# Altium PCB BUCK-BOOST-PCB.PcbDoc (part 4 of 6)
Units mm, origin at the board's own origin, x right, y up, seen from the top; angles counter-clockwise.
Board outline 99.9 x 67.48 mm, 4 copper layers (Top Layer, POWER, GND, Bottom Layer); 181 components, 110 nets, 560 pads, 389 vias.
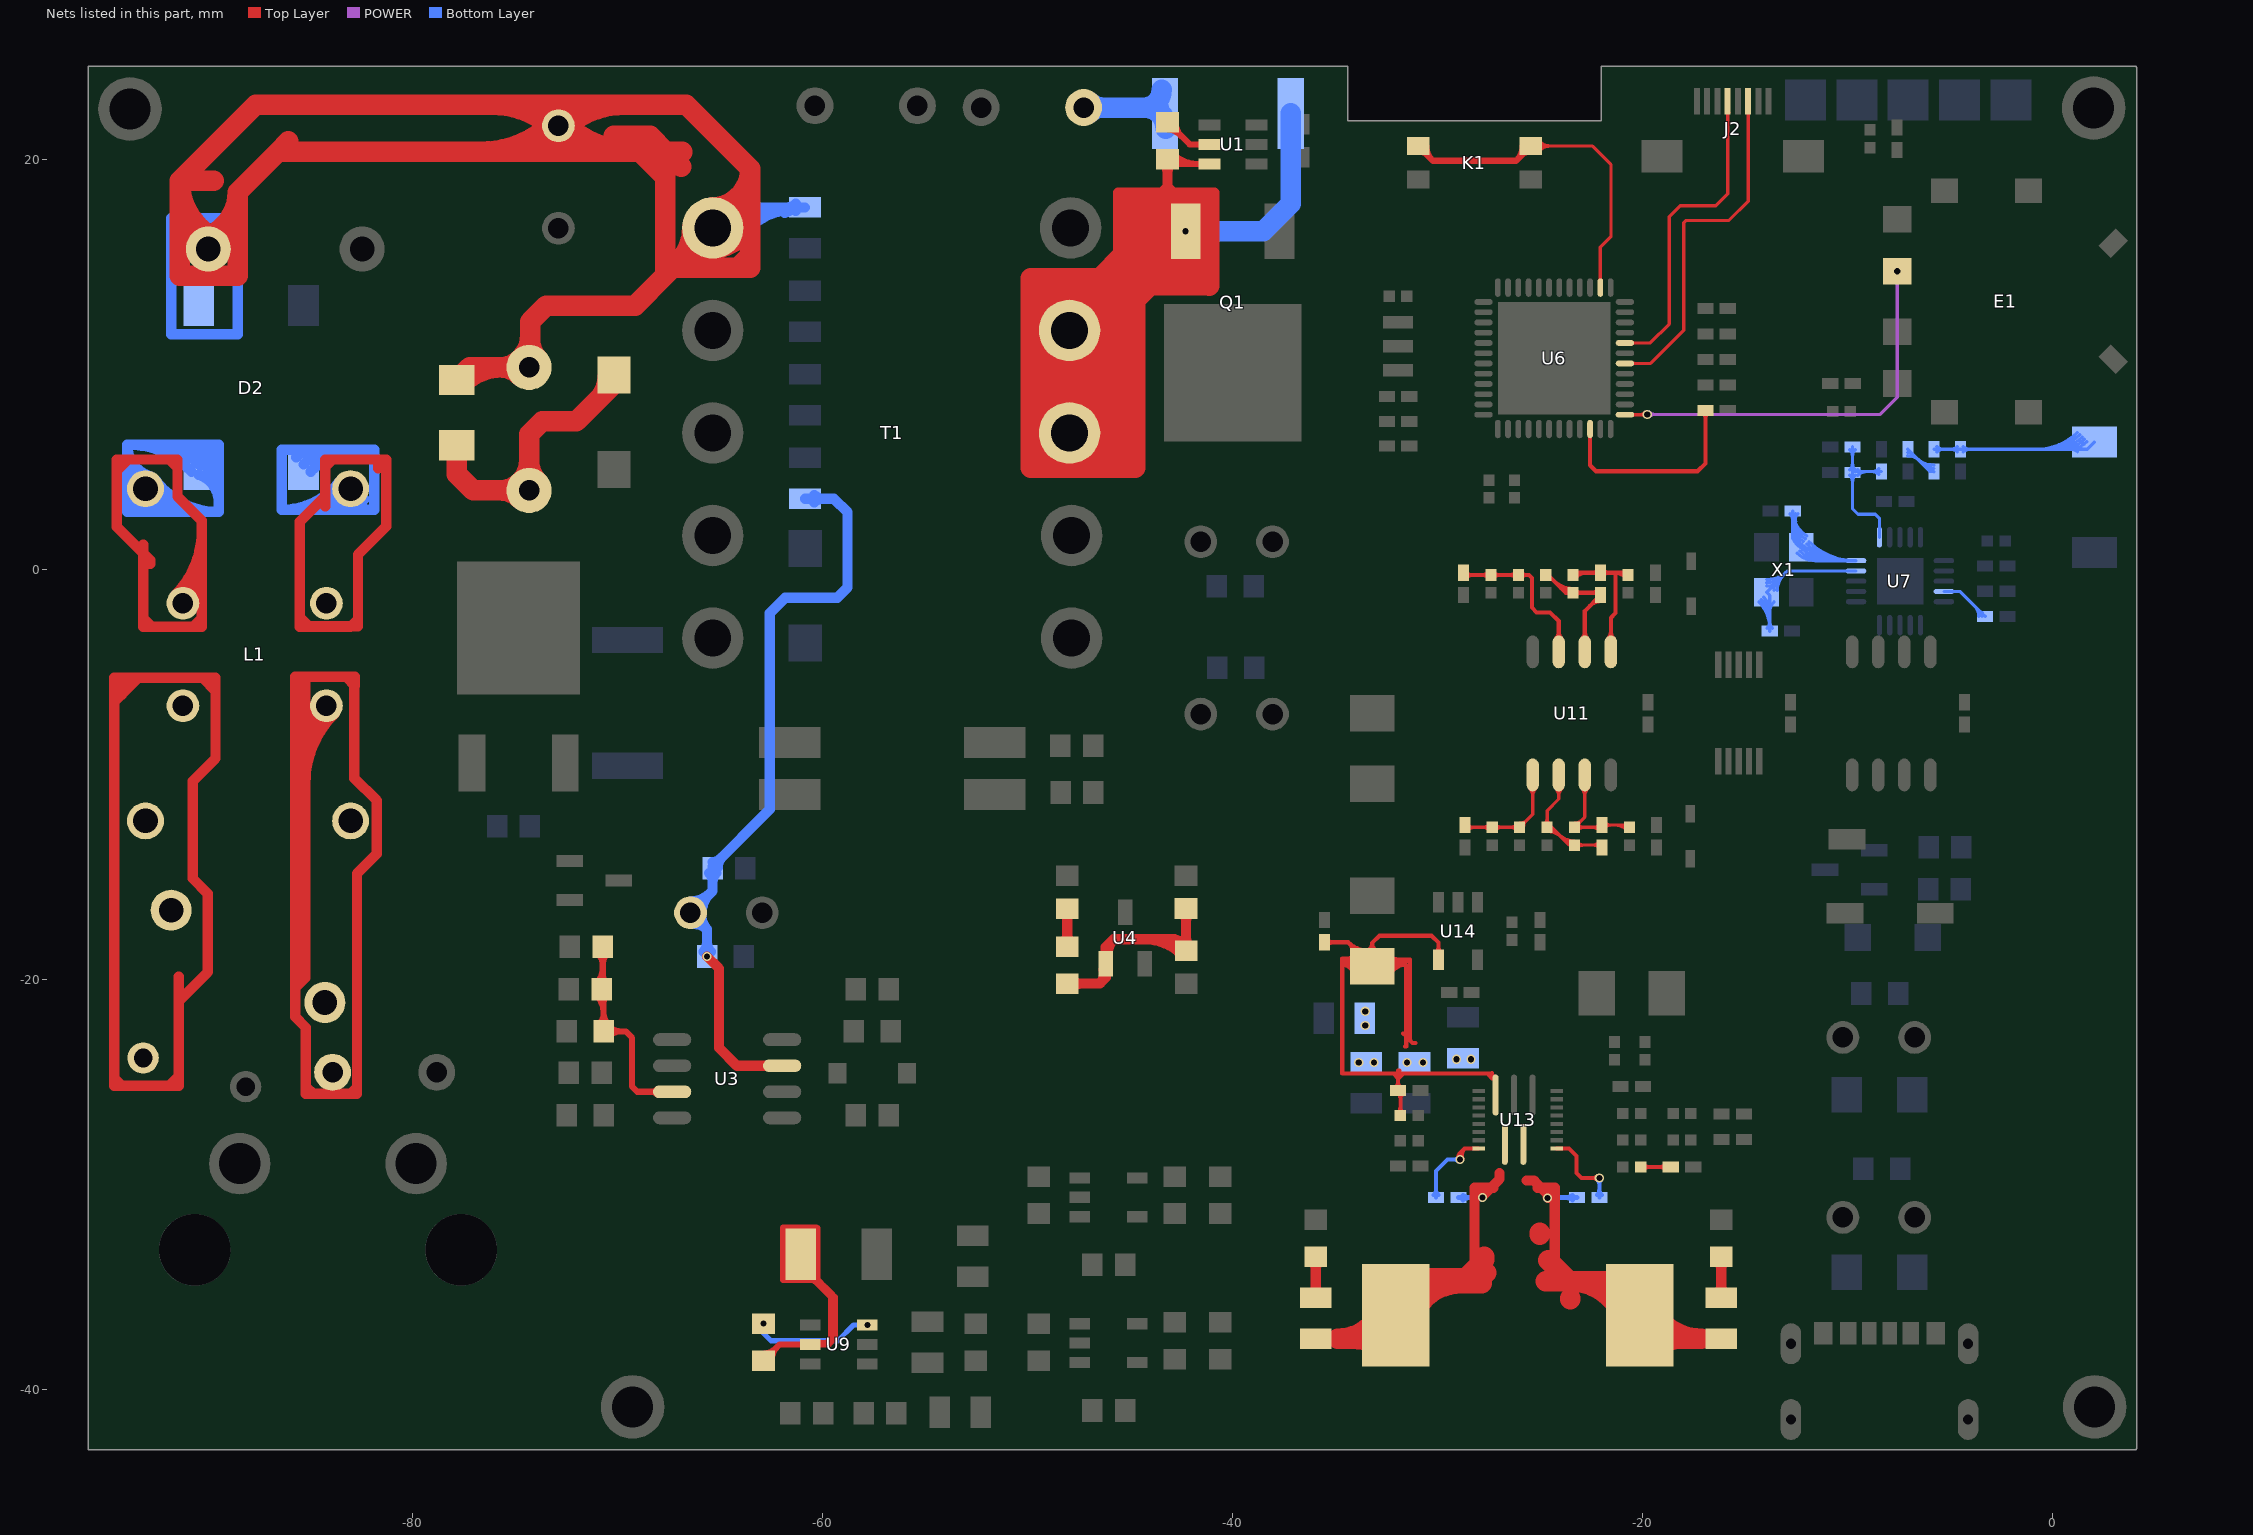
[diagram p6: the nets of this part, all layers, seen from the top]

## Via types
v1: diameter 0.45, hole 0.3, Top Layer to Bottom Layer, 389 vias

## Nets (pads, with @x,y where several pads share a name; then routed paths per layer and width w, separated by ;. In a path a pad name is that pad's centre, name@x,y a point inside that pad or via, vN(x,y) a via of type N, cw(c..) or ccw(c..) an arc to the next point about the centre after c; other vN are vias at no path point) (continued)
ISENSE: C15.2 R11.2 R19.2 U3.3 | length 17.4
  Top Layer w0.3: R11.2@-71.008,-20.762 cw(c-71.852,-21.605) -70.659,-21.605 ; R11.2@-71.008,-20.165 ccw(c-71.745,-19.428) -70.703,-19.428 ; R19.2@-70.951,-18.691 cw(c-71.549,-19.289) -70.703,-19.289 cw(c-69.858,-19.289) R19.2@-70.456,-18.691 ; C15.2@-70.907,-22.216 ccw(c-71.505,-21.618) -70.659,-21.618 ccw(c-69.813,-21.618) C15.2@-70.411,-22.216 ; -70.703,-19.705 ccw(c-70.053,-19.705) R11.2@-70.513,-20.165 ; R19.2@-70.703,-18.392 -70.703,-20.406 R11.2@-70.761,-20.463 -70.659,-20.565 C15.2@-70.659,-22.515 -69.583,-22.515 -69.27,-22.828 -69.27,-25.207 -69.017,-25.46 U3.3@-67.317,-25.46 ; -70.659,-21.115 cw(c-70.16,-21.115) R11.2@-70.513,-20.762 ; C15.2@-70.411,-22.763 cw(c-69.813,-23.361) -69.813,-22.515 cw(c-69.813,-21.669) C15.2@-70.411,-22.267 ; U3.3@-68.051,-25.576 ccw(c-68.332,-25.858) -68.332,-25.46 ccw(c-68.332,-25.061) U3.3@-68.051,-25.343
K1: E1.S U6.25 | length 21.7
  Top Layer w0.16: U6.25@-20.847,7.563 -19.773,7.563 v1(-19.759,7.577) ; U6.25@-20.495,7.52 cw(c-20.392,7.418) -20.392,7.563 cw(c-20.392,7.708) U6.25@-20.495,7.605 ; -20.143,7.563 ccw(c-20.143,7.961) v1@-19.861,7.679 ; -20.075,7.563 cw(c-20.075,7.261) v1@-19.861,7.474
  POWER w0.16: v1(-19.759,7.577) -8.402,7.577 -7.563,8.416 v1(-7.563,14.562) ; v1@-19.656,7.474 cw(c-19.409,7.227) -19.409,7.577 cw(c-19.409,7.927) v1@-19.656,7.679 ; v1@-7.665,14.46 cw(c-7.913,14.212) -7.563,14.212 cw(c-7.213,14.212) v1@-7.46,14.46
K2: K1.1 K1.2 U6.38 | length 21.1
  Top Layer w0.16: K1.2@-25.435,20.666 -22.426,20.666 -21.53,19.77 -21.53,16.245 -22.046,15.729 U6.38@-22.046,13.763 ; K1.2@-25.183,20.527 cw(c-24.845,20.189) -24.845,20.666 cw(c-24.845,21.143) K1.2@-25.183,20.806 ; K1.2@-25.069,20.413 cw(c-24.459,19.803) -24.459,20.666 cw(c-24.459,21.529) K1.2@-25.069,20.919 ; U6.38@-22.088,14.115 ccw(c-22.191,14.218) -22.046,14.218 ccw(c-21.901,14.218) U6.38@-22.004,14.115
  Top Layer w0.3: K1.1@-30.935,20.666 -30.215,19.947 -26.154,19.947 K1.2@-25.435,20.666 ; K1.1@-30.822,20.379 cw(c-30.822,19.956) K1.1@-30.524,20.255 ; K1.1@-30.535,20.666 ccw(c-29.569,20.666) -30.252,19.983 ; -26.118,19.983 ccw(c-26.8,20.666) K1.2@-25.835,20.666 ; K1.2@-25.846,20.255 cw(c-25.547,19.956) K1.2@-25.547,20.379
LCD_BCK: J2.3 U6.30 | length 17.7
  Top Layer w0.16: U6.30@-20.847,10.065 -19.595,10.065 -17.973,11.687 -17.973,16.921 -17.856,17.038 -15.773,17.038 -14.838,17.973 J2.3@-14.838,22.85 ; U6.30@-20.495,10.022 cw(c-20.392,9.92) -20.392,10.065 cw(c-20.392,10.21) U6.30@-20.495,10.107 ; J2.3@-14.887,22.301 cw(c-15.007,22.181) -14.838,22.181 cw(c-14.669,22.181) J2.3@-14.788,22.301
LCD_RST: J2.5 U6.32 | length 16.1
  Top Layer w0.16: U6.32@-20.847,11.063 -19.615,11.063 -18.693,11.985 -18.693,17.219 -18.154,17.758 -16.419,17.758 -15.838,18.339 J2.5@-15.838,22.85 ; U6.32@-20.495,11.02 cw(c-20.392,10.918) -20.392,11.063 cw(c-20.392,11.208) U6.32@-20.495,11.105 ; J2.5@-15.887,22.301 cw(c-16.007,22.181) -15.838,22.181 cw(c-15.669,22.181) J2.5@-15.788,22.301
MVCC: C12.1 C13.1 R5.2 R8.1 U3.7 | length 44.7
  Top Layer w0.5: v1(-65.616,-18.861) -65.033,-19.444 -65.033,-23.313 -64.157,-24.19 U3.7@-61.952,-24.19
  Bottom Layer w0.5: C13.1@-66.422,-16.18 ccw(c-66.422,-14.852) -65.483,-15.791 ccw(c-64.544,-16.73) C13.1@-65.872,-16.73 ; C13.1@-66.36,-17.276 cw(c-66.257,-18.178) -65.616,-17.536 ; C13.1@-65.876,-16.792 ccw(c-64.974,-16.894) -65.616,-17.536 ; C12.1@-65.793,-18.633 ccw(c-66.22,-18.205) -65.616,-18.205 ccw(c-65.011,-18.205) C12.1@-65.439,-18.633 ; v1(-65.616,-18.861) -65.616,-17.536 ; R5.2@-65.521,-14.786 cw(c-65.949,-15.213) -65.344,-15.213 cw(c-64.74,-15.213) R5.2@-65.167,-14.786 ; R5.2@-65.344,-14.257 ccw(c-65.344,-13.741) R5.2@-64.98,-14.106 ; R5.2@-65.094,-14.507 cw(c-64.4,-14.507) R5.2@-64.89,-14.017 ; R8.1@-60.834,3.466 -59.426,3.466 -58.76,2.8 -58.76,-0.86 -59.263,-1.363 -61.807,-1.363 -62.556,-2.112 -62.556,-11.683 -65.344,-14.47 R5.2@-65.344,-14.558 -65.344,-15.651 C13.1@-66.422,-16.73 -65.616,-17.536 ; R8.1@-60.383,3.289 cw(c-59.955,2.861) -59.955,3.466 cw(c-59.955,4.07) R8.1@-60.383,3.643
NetC1_2: C1.2 R1.1 | length 13.7
  Bottom Layer w0.5: R1.1@-43.573,22.545 R1.1@-43.283,22.254
  Bottom Layer w1: C1.2@-47.247,22.545 -44.307,22.545 ; C1.2@-46.964,22.262 cw(c-46.282,21.579) -46.282,22.545 cw(c-46.282,23.511) C1.2@-46.964,22.828 ; -44.325,22.545 cw(c-44.325,21.212) R1.1@-43.383,22.154 ; R1.1@-43.573,22.545 -44.289,22.545 ; R1.1@-43.438,23.414 cw(c-44.307,23.414) -44.289,22.545 ; R1.1@-43.245,21.501 ccw(c-44.289,21.501) -44.289,22.545 ; -44.307,22.545 cw(c-44.307,21.257) -43.384,22.156 ccw(c-44.307,21.257) -44.307,22.545 ; -44.307,22.545 ccw(c-44.307,23.414) -44.289,22.545 ; -44.307,22.545 -44.289,22.545 ; -44.288,22.545 cw(c-44.288,21.299) -43.385,22.157 ccw(c-44.288,21.299) -44.288,22.545
NetC2_1: C2.1 D1.2 R2.1 | length 19.3
  Top Layer w1: C2.1@-77.813,6.069 -77.813,4.667 -77.015,3.87 R2.1@-74.294,3.87 -74.294,6.612 -73.655,7.25 -71.984,7.25 -70.156,9.078 D1.2@-70.156,9.495 ; R2.1@-74.718,3.446 ccw(c-75.742,2.421) -75.742,3.87 ccw(c-75.742,5.318) -74.718,4.294 ccw(c-75.742,5.318) -74.294,5.318 ccw(c-72.845,5.318) R2.1@-73.869,4.294 ; -70.917,8.318 ccw(c-72.003,9.404) D1.2@-70.466,9.404
NetC2_2: C2.2 C10.1 C11.1 D2.1 R2.2 R3.2 T1.1 | length 194.4
  Top Layer w1: -91.33,17.298 ccw(c-89.052,17.298) C11.1@-90.126,15.29 ; C11.1@-90.119,16.214 ccw(c-90.819,18.42) -88.505,18.42 ; C11.1@-89.817,15.261 ccw(c-90.385,17.054) -88.505,17.054 ; -89.662,18.968 -91.33,18.968 ; C11.1@-89.655,16.172 cw(c-88.159,18.967) -91.33,18.967 ; -86.03,20.895 -86.537,20.389 ; C2.2@-77.813,9.254 -77.198,9.87 R2.2@-74.294,9.87 -74.243,9.921 -74.243,12.107 -73.463,12.887 -69.121,12.887 -67.645,14.362 ; C2.2@-77.52,9.083 cw(c-75.62,7.183) -75.62,9.87 ; -76.641,20.389 ccw(c-76.641,25.432) C10.1@-73.075,21.866 ; -76.062,22.678 cw(c-76.062,18.455) C10.1@-73.075,21.441 ; R2.2@-74.718,9.446 ccw(c-75.742,8.421) -75.742,9.87 ccw(c-75.742,11.318) -74.718,10.294 ccw(c-75.865,11.441) -74.243,11.441 ; -74.243,11.196 ccw(c-72.968,11.196) R2.2@-73.869,10.294 ; -74.227,20.389 ccw(c-74.227,23.018) C10.1@-72.368,21.159 ; -73.648,22.678 cw(c-73.648,20.869) C10.1@-72.368,22.148 ; C10.1@-73.358,21.159 ccw(c-71.499,23.018) -71.499,20.389 ; C10.1@-73.358,22.148 cw(c-72.078,20.869) -72.078,22.678 ; C10.1@-72.651,21.441 cw(c-69.664,18.455) -69.664,22.678 ; C10.1@-72.651,21.866 ccw(c-69.085,25.432) -69.085,20.389 ; -70.175,21.163 -69.659,21.163 ; -66.879,19.652 -67.616,20.389 ; -66.816,20.37 -66.835,20.389 -67.616,20.389 ; T1.1@-66.336,16.671 cw(c-68.751,16.671) -67.044,14.964 cw(c-65.336,13.257) T1.1@-65.336,15.671 ; T1.1@-65.355,17.671 ccw(c-65.391,19.552) -63.51,19.552 ; T1.1@-65.317,15.672 ccw(c-65.352,17.513) -63.51,17.513 ; -63.51,18.533 cw(c-65.372,18.533) -65.336,16.671 -67.187,14.821 ; -91.33,18.968 -91.33,14.333 -88.505,14.333 -88.505,18.42 ; -91.33,18.968 -87.619,22.678 -66.637,22.678 -63.51,19.552 ; -88.505,18.42 -86.537,20.389 ; -86.537,20.389 -68.885,20.389 ; -69.659,21.163 -68.391,21.163 -67.645,20.418 ; -69.659,21.163 -68.885,20.389 ; -68.885,20.389 -67.645,20.389 ; -68.885,20.389 -67.645,19.149 ; -67.645,14.362 -67.187,14.821 ; -67.645,14.362 -67.645,19.149 ; -67.645,19.149 -67.645,20.389 ; -67.645,20.389 -67.616,20.389 ; -67.645,20.389 -67.645,20.418 ; -67.645,20.418 -67.616,20.389 ; -67.187,14.821 -67.092,14.726 -64.077,14.726 ; -64.077,14.726 -63.51,14.726 -63.51,15.345 ; -64.077,14.726 -64.077,14.779 -63.51,15.345 ; -63.51,15.345 -63.51,19.552
  Bottom Layer w0.5: T1.1@-65.536,16.821 cw(c-63.835,15.545) -63.835,17.672 ; T1.1@-65.336,16.671 -64.336,17.672 R3.2@-60.834,17.672 ccw(c-60.834,13.294) T1.1@-64.336,15.921 ; T1.1@-65.136,16.521 cw(c-62.835,14.795) -62.835,17.672 ; T1.1@-64.736,16.221 cw(c-61.835,14.045) -61.835,17.672 ; -61.837,17.404 ccw(c-62.055,18.218) R3.2@-61.324,17.797 ; R3.2@-61.285,17.496 ccw(c-61.71,17.071) -61.71,17.672 ccw(c-61.71,18.274) R3.2@-61.285,17.848 ; -91.744,11.481 -91.744,17.146 -88.505,17.146 -88.505,11.481 -91.744,11.481
NetC3_1: C3.1 Q1.3 R1.2 T1.8 T1.9 U1.3 | length 292.7
  Top Layer w0.3: C3.1@-43.156,20.019 -42.93,19.793 U1.3@-41.12,19.793 ; C3.1@-43.069,20.055 ccw(c-42.438,20.686) -42.438,19.793 ; C3.1@-42.857,20.267 ccw(c-41.714,21.411) -41.714,19.793 ; Q1.3@-42.479,17.671 ccw(c-42.593,17.969) -42.273,17.969 ; v1(-42.273,16.509) -42.273,17.969 ; Q1.3@-42.068,17.671 cw(c-41.954,17.969) -42.273,17.969 ; U1.3@-41.472,19.711 ccw(c-41.67,19.513) -41.67,19.793 ccw(c-41.67,20.073) U1.3@-41.472,19.875
  Top Layer w0.5: -45.556,17.832 -45.556,18.398 -43.437,18.398 ; -44.172,17.969 -43.866,17.969 -43.437,18.398 ; C3.1@-43.333,19.842 cw(c-43.754,19.421) -43.158,19.421 ; -43.158,17.002 -43.158,17.969 -43.158,18.398 ; -43.158,18.109 ccw(c-42.15,18.109) Q1.3@-42.276,17.109 ; -43.158,19.408 cw(c-42.545,19.408) C3.1@-42.979,19.842 ; C3.1@-43.156,20.019 -43.158,20.019 -43.158,18.677 ; -42.816,18.398 -42.88,18.398 ; Q1.3@-42.214,17.605 cw(c-42.078,18.677) -43.158,18.677 ; -40.876,17.892 -40.876,18.398 -42.88,18.398 ; -43.437,18.398 -43.158,18.398 ; -43.437,18.398 -43.158,18.677 ; -43.158,18.398 -42.88,18.398 ; -43.158,18.398 -43.158,18.677 ; -43.158,18.677 -42.88,18.398
  Top Layer w1: -49.818,7.129 cw(c-43.395,7.129) T1.9@-47.937,11.671 ; -49.818,8.799 ccw(c-45.809,8.799) T1.8@-48.644,5.964 ; -49.818,9.543 cw(c-45.809,9.543) T1.9@-48.644,12.378 ; -49.818,11.214 ccw(c-43.395,11.214) T1.8@-47.937,6.671 ; -49.818,13.628 ccw(c-40.98,13.628) -47.23,7.378 cw(c-42.857,11.751) T1.9@-49.041,11.751 ; -49.643,5.712 cw(c-46.93,5.234) T1.8@-48.511,7.49 ; -49.547,6.257 cw(c-47.857,5.96) T1.8@-48.048,7.665 ; T1.8@-49.041,6.591 cw(c-42.857,6.591) T1.9@-47.23,10.964 ; -49.041,9.006 cw(c-45.271,9.006) T1.9@-47.937,11.671 ; -49.041,9.337 ccw(c-45.271,9.337) T1.8@-47.937,6.671 ; -49.041,13.007 ccw(c-47.681,13.007) T1.9@-47.937,11.671 ; -49.016,8.179 ccw(c-47.539,7.281) T1.8@-48.483,5.834 ; T1.9@-48.596,12.423 ccw(c-49.87,13.877) -47.937,13.877 ; T1.8@-48.493,7.502 ccw(c-49.501,9.007) -47.94,9.924 ; -48.48,9.061 ccw(c-46.975,8.146) T1.8@-47.937,6.671 ; T1.9@-47.977,12.671 ccw(c-48.019,13.683) -47.005,13.683 ; -47.943,9.943 ccw(c-46.41,9.011) T1.8@-47.39,7.509 ; T1.9@-47.749,12.654 cw(c-47.45,14.216) -49.041,14.216 ; T1.8@-47.695,7.642 cw(c-48.126,5.911) -46.365,6.193 ; T1.9@-47.48,12.561 cw(c-46.628,14.216) -48.49,14.216 ; -47.402,9.009 cw(c-48.91,8.124) T1.8@-47.937,6.671 ; T1.8@-47.38,5.841 ccw(c-48.318,7.24) -46.865,8.094 ; T1.8@-47.35,7.481 cw(c-48.89,5.355) -46.298,5.77 ; T1.9@-47.278,12.423 cw(c-46.004,13.877) -47.937,13.877 ; T1.8@-47.23,5.964 ccw(c-49.777,8.511) -46.175,8.511 ; T1.9@-47.23,12.378 cw(c-49.777,9.831) -46.175,9.831 ; T1.9@-47.123,12.253 cw(c-46.221,12.898) -47.005,13.683 ; T1.8@-47.005,7.008 ccw(c-52.6,7.008) -48.644,10.964 cw(c-54.605,5.003) -46.175,5.003 ; -47.005,8.92 cw(c-50.186,8.92) T1.8@-47.937,6.671 ; -47.005,9.422 ccw(c-50.186,9.422) T1.9@-47.937,11.671 ; T1.9@-47.005,11.335 cw(c-52.6,11.335) -48.644,7.378 ccw(c-54.605,13.34) -46.175,13.34 ; -46.175,7.417 ccw(c-52.191,7.417) T1.9@-47.937,11.671 ; -46.175,10.926 cw(c-52.191,10.926) T1.8@-47.937,6.671 ; -45.543,12.325 -45.305,12.564 ; -43.866,17.969 -43.721,17.969 ; -43.158,14.192 cw(c-41.54,14.192) Q1.3@-42.184,15.677 ; -43.158,15.761 cw(c-42.26,15.761) Q1.3@-42.356,16.654 ; -43.158,16.875 cw(c-42.38,16.875) Q1.3@-42.464,17.649 ; -43.158,17.002 -43.158,15.02 ; Q1.3@-42.355,15.674 cw(c-43.062,13.864) -41.119,13.864 ; Q1.3@-42.283,15.659 cw(c-42.337,14.442) -41.119,14.442 ; Q1.3@-42.195,17.657 cw(c-42.245,16.532) -41.119,16.532 ; Q1.3@-42.048,15.897 ccw(c-41.119,15.952) -41.119,15.02 ; Q1.3@-42.049,17.115 cw(c-41.119,17.036) -41.119,17.969 ; Q1.3@-41.991,16.606 cw(c-42.49,15.328) -41.119,15.328 ; -41.171,17.941 -41.171,17.969 ; -49.041,4.967 -49.818,4.967 -49.818,14.216 -49.041,14.216 ; -49.041,4.967 -49.041,14.216 ; -49.041,4.967 -47.005,4.967 ; -49.041,14.216 -48.49,14.216 ; -48.49,14.216 -47.937,14.216 ; -48.49,14.216 -48.49,11.671 T1.9@-47.937,11.671 ; T1.9@-47.937,11.671 T1.9@-47.937,12.751 ; T1.9@-47.937,12.751 -47.005,13.683 ; T1.9@-47.937,12.751 -47.937,13.877 ; -47.937,13.877 -47.832,13.877 ; -47.937,13.877 -47.937,14.216 ; -47.937,14.216 -47.832,14.216 -47.832,13.877 ; -47.937,14.216 -47.937,14.227 -47.005,14.227 ; -47.832,13.877 -47.005,13.877 ; -47.005,4.967 -46.175,4.967 ; -47.005,4.967 -47.005,13.683 ; -47.005,13.683 -46.811,13.877 ; -47.005,13.683 -47.005,13.877 ; -47.005,13.877 -47.005,14.227 ; -47.005,13.877 -46.811,13.877 ; -47.005,14.227 -46.462,14.227 ; -46.811,13.877 -46.462,14.227 ; -46.811,13.877 -46.175,13.877 ; -46.462,14.227 -45.305,15.384 ; -46.462,14.227 -46.175,14.227 ; -46.175,4.967 -45.305,4.967 ; -46.175,4.967 -46.175,13.877 ; -46.175,13.877 -46.175,14.227 ; -46.175,13.877 -45.305,13.877 ; -46.175,14.227 -45.305,14.227 ; -45.305,4.967 -44.729,4.967 -44.729,13.139 ; -45.305,4.967 -45.305,12.564 ; -45.305,12.564 -44.729,13.139 ; -45.305,12.564 -45.305,13.877 ; -45.305,13.877 -45.305,14.227 ; -45.305,13.877 -44.729,13.877 ; -45.305,14.227 -44.729,14.227 ; -45.305,14.227 -45.305,15.384 ; -45.305,15.384 -45.305,17.969 -44.743,17.969 ; -44.743,17.969 -44.172,17.969 -44.172,14.227 ; -44.743,17.969 -44.743,14.241 -44.729,14.227 ; -44.729,13.139 -43.992,13.877 ; -44.729,13.139 -44.729,13.877 ; -44.729,13.877 -44.729,14.227 ; -44.729,13.877 -43.992,13.877 ; -44.729,14.227 -44.172,14.227 ; -44.172,14.227 -43.642,14.227 ; -43.992,13.877 -43.642,14.227 ; -43.992,13.877 -41.119,13.877 -41.119,14.227 ; -43.721,17.969 -43.158,17.969 -42.273,17.969 -41.171,17.969 ; -43.721,17.969 -43.721,14.443 -43.426,14.443 ; -43.642,14.227 -41.119,14.227 ; -43.642,14.227 -43.426,14.443 ; -43.426,14.443 -43.158,14.443 -43.158,15.02 ; -43.158,15.02 -41.119,15.02 ; -41.171,17.969 -41.119,17.969 ; -41.119,14.227 -41.119,15.02 ; -41.119,15.02 -41.119,17.969 ; -43.158,14.647 cw(c-42.14,14.647) -42.249,15.66 ccw(c-42.14,14.647) -43.158,14.647 ; Q1.3@-42.239,16.658 cw(c-42.291,15.487) -41.119,15.487 ccw(c-42.291,15.487) Q1.3@-42.239,16.658
  Top Layer w2: T1.8@-47.937,6.671 T1.9@-47.937,11.671
  Bottom Layer w1: v1(-42.273,16.509) -38.486,16.509 -37.15,17.845 R1.2@-37.15,22.254
NetC3_2: C3.2 U1.2 | length 4.3
  Top Layer w0.3: C3.2@-43.156,21.82 -42.079,20.743 U1.2@-41.12,20.743 ; C3.2@-43.105,21.47 cw(c-43.105,20.746) -42.594,21.258 ; C3.2@-42.755,21.82 ccw(c-41.786,21.82) -42.471,21.135 ; U1.2@-41.472,20.661 ccw(c-41.67,20.463) -41.67,20.743 ccw(c-41.67,21.023) U1.2@-41.472,20.825
NetC5_1: C5.1 L1.2 NTC1.2 Z1.2 | length 58.1
  Top Layer w0.5: -91.387,-19.84 -91.387,-20.978 ; -94.522,-24.787 -94.146,-25.162 ; -94.522,-24.787 -94.522,-25.162 -94.146,-25.162 ; -94.522,-24.787 -94.522,-6.43 ; -94.522,-6.43 -94.522,-5.268 -94.144,-5.268 ; -94.522,-6.43 -94.193,-6.101 ; -94.193,-6.101 -94.144,-6.101 -94.144,-6.051 ; -94.193,-6.101 -94.144,-6.051 ; -94.146,-25.162 -91.846,-25.162 ; -94.144,-6.051 -94.144,-5.268 ; -94.144,-6.051 -93.362,-5.269 -93.359,-5.272 -90.216,-5.272 -89.592,-5.895 ; -94.144,-5.268 -89.592,-5.268 -89.592,-5.895 ; -91.846,-25.162 -91.387,-24.703 ; -91.846,-25.162 -91.387,-25.162 -91.387,-24.703 ; -91.387,-24.703 -91.387,-20.978 ; -91.387,-20.978 -91.317,-20.978 -89.962,-19.623 -89.962,-15.795 -90.698,-15.058 -90.698,-10.314 -89.592,-9.207 -89.592,-5.895
NetC5_2: C5.2 F1.1 L1.3 Z1.1 | length 75.1
  Top Layer w0.5: -85.207,-10.448 cw(c-80.36,-10.448) L1.3@-83.788,-7.021 ; -85.207,-9.241 cw(c-81.567,-9.241) L1.3@-84.141,-6.667 ; -85.207,-8.034 cw(c-82.774,-8.034) L1.3@-84.495,-6.314 ; -83.56,-25.54 -82.968,-25.54 ; -85.701,-20.389 -85.207,-19.895 -85.207,-5.371 -85.058,-5.222 ; -85.701,-20.389 -85.701,-5.222 -85.058,-5.222 ; -85.701,-20.389 -85.701,-21.805 -85.183,-22.323 -85.183,-25.206 ; -85.183,-25.206 -84.828,-25.56 ; -85.183,-25.206 -85.183,-25.56 -84.828,-25.56 ; -85.058,-5.222 -85.054,-5.218 -83.228,-5.218 -83.224,-5.222 ; -85.058,-5.222 -83.224,-5.222 ; -84.828,-25.56 -82.988,-25.56 ; -83.224,-5.222 -82.795,-5.222 -82.795,-5.651 ; -83.224,-5.222 -82.795,-5.651 ; -82.988,-25.56 -82.968,-25.54 ; -82.988,-25.56 -82.692,-25.56 -82.692,-25.264 ; -82.968,-25.54 -82.692,-25.264 ; -82.795,-5.651 -82.817,-5.673 -82.817,-10.162 -81.73,-11.25 -81.73,-13.854 -82.692,-14.817 -82.692,-25.264
NetC6_1: C6.1 D2.3 L1.4 | length 60.1
  Top Layer w0.5: -84.773,-2.777 -85.477,-2.777 -85.477,-2.318 ; -84.243,3.094 -84.238,3.099 -84.238,3.585 ; -81.834,5.38 -83.872,5.38 -84.238,5.014 ; -81.648,4.934 -81.648,5.384 ; -81.512,5.384 -81.648,5.384 ; -85.477,-2.318 -85.018,-2.777 ; -85.477,-2.318 -85.477,2.36 -85.463,2.36 -84.238,3.585 ; -85.018,-2.777 -82.998,-2.777 -82.991,-2.77 ; -85.018,-2.777 -84.991,-2.751 -82.991,-2.751 ; -84.238,3.585 -84.238,5.014 ; -84.238,5.014 -84.238,5.384 -81.648,5.384 ; -82.991,-2.77 -82.972,-2.751 ; -82.991,-2.77 -82.991,-2.771 -82.644,-2.771 -82.644,-2.423 ; -82.991,-2.77 -82.991,-2.751 ; -82.991,-2.751 -82.972,-2.751 ; -82.972,-2.751 -82.644,-2.423 ; -82.644,-2.423 -82.644,0.728 -81.257,2.115 -81.257,5.384 -81.648,5.384
  Bottom Layer w0.5: D2.3@-86.007,5.839 cw(c-85.971,5.803) D2.3@-85.971,5.854 ; D2.3@-85.653,5.485 cw(c-84.764,4.596) D2.3@-84.764,5.854 ; -85.362,2.925 ccw(c-85.362,5.726) C6.1@-83.121,4.045 ; D2.3@-85.3,5.132 cw(c-83.557,3.389) -83.557,5.854 ; D2.3@-84.946,4.778 cw(c-82.35,2.182) -82.35,5.854 ; -84.362,2.925 ccw(c-84.362,4.976) C6.1@-82.721,3.745 ; C6.1@-83.521,4.345 cw(c-86.362,6.477) -86.362,2.925 ; -83.361,2.925 ccw(c-83.361,4.225) C6.1@-82.321,3.445 ; -86.363,2.925 -81.85,2.925 -81.85,5.854 -86.363,5.854 -86.363,2.925
NetC6_2: C6.2 D2.4 L1.1 | length 78
  Top Layer w0.5: -93.109,1.235 -93.109,0.803 ; -92.771,0.285 -92.771,0.465 -93.109,0.803 ; L1.1@-91.565,-1.243 ccw(c-94.726,1.918) -90.256,1.918 ; L1.1@-91.212,-1.597 ccw(c-93.519,0.71) -90.256,0.71 ; L1.1@-90.858,-1.95 ccw(c-92.312,-0.497) -90.256,-0.497 ; -94.399,4.827 -93.85,5.376 ; -94.399,4.827 -94.399,5.376 -93.85,5.376 ; -94.399,4.827 -94.399,2.093 -93.109,0.803 ; -93.85,5.376 -91.812,5.376 ; -93.109,-2.358 -92.686,-2.781 ; -93.109,-2.358 -93.109,-2.781 -92.686,-2.781 ; -93.109,-2.358 -93.109,0.803 ; -92.686,-2.781 -90.667,-2.781 ; -91.812,5.376 -91.812,5.352 -91.446,4.986 ; -91.812,5.376 -91.446,5.376 -91.446,4.986 ; -91.446,4.986 -91.446,3.578 -90.256,2.388 -90.256,-2.371 ; -90.667,-2.781 -90.256,-2.371 ; -90.667,-2.781 -90.256,-2.781 -90.256,-2.371
  Bottom Layer w0.5: -93.891,4.71 ccw(c-92.743,4.71) C6.2@-93.115,3.624 ; -93.891,5.409 ccw(c-92.504,5.409) C6.2@-92.953,4.097 ; C6.2@-93.682,3.445 ccw(c-92.426,4.386) -92.426,2.817 ; C6.2@-93.281,3.745 ccw(c-91.427,5.134) -91.427,2.817 ; C6.2@-92.881,4.045 ccw(c-90.428,5.882) -90.428,2.817 ; C6.2@-92.791,4.57 cw(c-92.265,6.109) -93.891,6.109 ; -92.709,6.109 cw(c-92.709,2.893) D2.4@-90.401,5.132 ; C6.2@-92.481,4.345 ccw(c-89.429,6.631) -89.429,2.817 ; -91.528,6.109 cw(c-91.528,4.039) D2.4@-90.042,5.48 ; D2.4@-90.76,4.784 ccw(c-93.891,1.747) -93.891,6.109 ; D2.4@-90.401,4.634 cw(c-90.867,3.273) -89.428,3.273 ; -90.346,6.109 cw(c-90.346,5.184) D2.4@-89.683,5.828 ; D2.4@-90.239,5.107 cw(c-90.627,3.973) -89.428,3.973 ; D2.4@-90.077,5.58 cw(c-90.387,4.673) -89.428,4.673 ; -93.891,6.109 -89.428,6.109 -89.428,2.817 ; -93.891,6.109 -93.891,2.817 -89.428,2.817
NetC16_1: C16.1 R17.2 R20.2 U4.1 | length 18.4
  Top Layer w0.5: C16.1@-48.049,-20.18 -46.459,-20.18 ; C16.1@-47.821,-20.357 cw(c-47.394,-20.785) -47.394,-20.18 cw(c-47.394,-19.576) C16.1@-47.821,-20.003 ; U4.1@-46.264,-19.503 cw(c-46.975,-19.665) -46.459,-20.18 ; U4.1@-46.067,-18.915 cw(c-45.049,-18.747) -45.778,-18.017 ; -44.265,-18.017 cw(c-44.265,-20.543) R20.2@-42.479,-18.757 ; -43.058,-18.017 cw(c-43.058,-19.336) R20.2@-42.126,-18.404 ; -42.766,-18.066 cw(c-43.28,-18.58) R20.2@-42.553,-18.58 ; R20.2@-42.643,-18.189 ccw(c-42.302,-17.848) R20.2@-42.302,-18.33 ; R17.2@-42.434,-16.697 cw(c-42.873,-17.137) -42.252,-17.137 ; R20.2@-42.429,-18.403 ccw(c-42.856,-17.976) -42.252,-17.976 ccw(c-41.647,-17.976) R20.2@-42.075,-18.403 ; R17.2@-42.257,-16.52 -42.252,-16.525 R20.2@-42.252,-18.58 -42.814,-18.017 -45.778,-18.017 ; -42.252,-17.112 cw(c-41.665,-17.112) R17.2@-42.08,-16.697 ; -46.459,-20.18 -46.166,-19.887 U4.1@-46.166,-19.206 -46.166,-18.405 -45.778,-18.017
NetC16_2: C16.2 R16.1 | length 3.8
  Top Layer w0.5: C16.2@-48.226,-18.202 ccw(c-48.66,-17.769) -48.047,-17.769 ; R16.1@-48.224,-16.7 cw(c-48.651,-17.127) -48.047,-17.127 cw(c-47.442,-17.127) R16.1@-47.87,-16.7 ; C16.2@-48.049,-18.379 -48.047,-18.377 R16.1@-48.047,-16.523 ; -48.047,-17.781 ccw(c-47.451,-17.781) C16.2@-47.872,-18.202
NetC22_2: C22.2 U7.19 | length 3.5
  Bottom Layer w0.16: U7.19@-5.291,-1.057 -4.507,-1.057 -3.291,-2.273 C22.2@-3.279,-2.273 ; -3.809,-1.755 cw(c-4.327,-2.273) C22.2@-3.594,-2.273 ; C22.2@-3.434,-2.273 ccw(c-3.781,-2.273) -3.536,-2.028 ccw(c-3.404,-1.898) C22.2@-3.404,-2.083
NetC26_1: C26.1 L2.2 | length 4.6
  Bottom Layer w0.16: L2.2@-7.052,5.563 cw(c-7.052,4.802) -6.514,5.34 ; L2.2@-7.052,5.723 cw(c-7.052,5.349) L2.2@-6.787,5.613 ; L2.2@-7.052,5.878 -5.962,4.788 C26.1@-5.771,4.788 ; -6.635,5.461 ccw(c-5.771,6.325) C26.1@-5.771,5.103 ; -6.362,5.188 ccw(c-5.771,5.779) C26.1@-5.771,4.943 ; -6.089,4.915 ccw(c-5.771,5.232) C26.1@-5.771,4.783
NetC26_2: C26.2 C28.2 F3.1 | length 18.4
  Bottom Layer w0.16: C26.2@-5.771,5.878 C28.2@-4.489,5.878 1.701,5.878 F3.1@2.049,6.226 ; C26.2@-5.636,5.744 cw(c-5.312,5.419) -5.312,5.878 cw(c-5.312,6.337) C26.2@-5.636,6.012 ; C28.2@-4.624,5.744 ccw(c-4.948,5.419) -4.948,5.878 ccw(c-4.948,6.337) C28.2@-4.624,6.012 ; C28.2@-4.355,5.744 cw(c-4.031,5.419) -4.031,5.878 cw(c-4.031,6.337) C28.2@-4.355,6.012 ; -0.759,5.878 ccw(c-0.759,8.684) F3.1@1.225,6.7 ; -0.373,5.878 ccw(c-0.373,8.298) F3.1@1.338,6.587 ; 0.014,5.878 ccw(c0.014,7.911) F3.1@1.451,6.473 ; 0.4,5.878 ccw(c0.4,7.525) F3.1@1.565,6.36 ; 0.786,5.878 ccw(c0.786,7.139) F3.1@1.678,6.247 ; 0.92,5.878 cw(c0.92,5.446) F3.1@1.225,5.751
NetC29_1: C29.1 C30.1 L4.2 U7.11 | length 10.5
  Bottom Layer w0.16: C30.1@-9.883,4.606 cw(c-10.207,4.281) -9.749,4.281 cw(c-9.29,4.281) C30.1@-9.614,4.606 ; C30.1@-9.883,4.874 ccw(c-10.207,5.199) -9.749,5.199 ccw(c-9.29,5.199) C30.1@-9.614,4.874 ; C29.1@-9.883,5.861 cw(c-10.207,5.536) -9.749,5.536 cw(c-9.29,5.536) C29.1@-9.614,5.861 ; C29.1@-9.749,5.995 C30.1@-9.749,4.74 ; C30.1@-9.489,4.606 cw(c-9.05,4.166) -9.05,4.788 ; C30.1@-9.489,4.874 ccw(c-9.28,5.084) -9.28,4.788 ; L4.2@-8.468,4.653 ccw(c-8.792,4.329) -8.792,4.788 ccw(c-8.792,5.247) L4.2@-8.468,4.922 ; U7.11@-8.434,1.586 -8.434,2.514 -8.633,2.714 -9.481,2.714 -9.749,2.982 C30.1@-9.749,4.74 ; L4.2@-8.333,4.788 -9.701,4.788 C30.1@-9.749,4.74
NetC32_1: C32.1 U7.10 X1.3 | length 23.3
  Bottom Layer w0.16: C32.1@-12.795,2.736 cw(c-13.119,2.412) -12.66,2.412 cw(c-12.202,2.412) C32.1@-12.526,2.736 ; X1.3@-12.66,1.735 ccw(c-11.92,1.735) X1.3@-12.303,1.102 ; -12.66,2.019 ccw(c-11.748,2.019) X1.3@-12.22,1.238 ; -12.66,2.303 ccw(c-11.577,2.303) X1.3@-12.138,1.375 ; -12.66,2.586 ccw(c-11.405,2.586) X1.3@-12.055,1.512 ; -12.523,2.359 cw(c-12.173,2.453) C32.1@-12.411,2.727 ; X1.3@-12.439,0.806 ccw(c-11.563,1.682) -11.563,0.443 ; X1.3@-12.326,0.919 ccw(c-11.177,2.069) -11.177,0.443 ; X1.3@-12.213,1.033 ccw(c-10.79,2.455) -10.79,0.443 ; X1.3@-12.1,1.146 ccw(c-10.404,2.841) -10.404,0.443 ; X1.3@-12.096,0.675 cw(c-11.969,0.386) X1.3@-11.746,0.609 ; X1.3@-12.032,0.528 cw(c-11.868,0.156) -11.58,0.443 ; X1.3@-11.986,1.259 ccw(c-10.018,3.227) U7.10@-10.018,0.443 ; X1.3@-11.972,1.649 cw(c-11.233,2.87) C32.1@-12.66,2.87 -12.66,1.524 X1.3@-12.241,1.104 -11.58,0.443 ; X1.3@-11.873,1.372 ccw(c-9.632,3.614) U7.10@-9.632,0.443 ; X1.3@-11.729,0.914 ccw(c-11.202,0.822) -11.58,0.443 ; U7.10@-9.577,0.443 -11.58,0.443
NetC34_1: C34.1 U7.9 X1.1 | length 15.2
  Bottom Layer w0.16: X1.1@-14.309,-1.563 cw(c-15.574,-2.829) C34.1@-13.785,-2.829 ; X1.1@-14.196,-1.45 cw(c-15.188,-2.443) -13.785,-2.443 ; X1.1@-14.082,-1.337 cw(c-14.802,-2.056) -13.785,-2.056 ; X1.1@-13.938,-0.796 ccw(c-13.929,-0.101) X1.1@-13.438,-0.592 ; X1.1@-13.936,-0.636 ccw(c-13.921,0.427) -13.17,-0.325 ; X1.1@-13.934,-0.476 ccw(c-13.914,0.956) -12.902,-0.057 ; C34.1@-13.919,-2.86 ccw(c-14.243,-2.536) -13.785,-2.536 ccw(c-13.326,-2.536) C34.1@-13.65,-2.86 ; C34.1@-13.785,-2.995 -13.785,-1.252 X1.1@-13.941,-1.096 -12.902,-0.057 ; -13.785,-2.073 cw(c-13.063,-2.073) X1.1@-13.573,-1.563 ; X1.1@-13.581,-0.996 cw(c-12.953,-0.996) X1.1@-13.397,-0.552 ; X1.1@-13.421,-0.996 cw(c-12.407,-0.996) -13.124,-0.279 ; U7.9@-9.577,-0.057 -12.902,-0.057
NetC38_1: C38.1 U6.22 | length 10.9
  Top Layer w0.2: U6.22@-22.546,6.864 -22.546,5.098 -22.253,4.804 -17.305,4.804 -16.922,5.187 C38.1@-16.922,7.778 ; C38.1@-17.042,7.658 cw(c-17.333,7.367) -16.922,7.367 cw(c-16.512,7.367) C38.1@-16.802,7.658
NetC39_1: C39.1 U9.6 | length 6.8
  Bottom Layer w0.254: v1@-62.932,-36.837 cw(c-63.099,-37.005) -62.862,-37.005 cw(c-62.626,-37.005) v1@-62.793,-36.837 ; v1(-62.862,-36.768) -62.862,-37.236 -62.498,-37.601 -59.243,-37.601 -58.474,-36.832 v1(-57.791,-36.832) ; v1@-57.861,-36.902 ccw(c-58.028,-37.069) -58.028,-36.832 ccw(c-58.028,-36.596) v1@-57.861,-36.763
NetC39_2: C39.2 L5.1 U9.2 | length 38.4
  Top Layer w0.3: C39.2@-62.862,-38.569 -62.076,-37.782 U9.2@-60.591,-37.782 -59.861,-37.782 ; C39.2@-62.812,-38.218 ccw(c-62.812,-37.495) -62.3,-38.007 ; C39.2@-62.461,-38.569 cw(c-61.493,-38.569) -62.178,-37.884 ; L5.1@-61.041,-33.379 -61.041,-33.819 -60.232,-34.628 ; U9.2@-60.905,-37.871 ccw(c-61.118,-38.084) -61.118,-37.782 ccw(c-61.118,-37.481) U9.2@-60.905,-37.694 ; L5.1@-60.741,-33.879 ccw(c-59.749,-33.879) L5.1@-60.451,-34.581 ; L5.1@-60.684,-34.347 -60.385,-34.647 ; U9.2@-60.517,-37.72 -59.799,-37.72 ; U9.2@-60.278,-37.871 cw(c-60.065,-38.084) -60.065,-37.782 cw(c-60.065,-37.481) U9.2@-60.278,-37.694 ; -60.206,-34.825 ccw(c-61.041,-35.66) -61.041,-34.479 cw(c-61.041,-36.074) -59.914,-34.946 ; -60.06,-34.8 cw(c-59.139,-33.879) -60.441,-33.879 ccw(c-58.725,-33.879) -59.938,-35.093 ; -60.385,-34.647 cw(c-60.041,-34.303) -60.489,-34.113 ccw(c-60.041,-34.303) -60.385,-34.647 ; -60.385,-34.647 ccw(c-60.832,-35.094) -60.939,-34.471 cw(c-60.832,-35.094) -60.385,-34.647 ; -60.385,-34.647 -60.213,-34.647 ; -60.385,-34.647 -61.905,-34.647 -61.905,-32.084 -60.279,-32.084 -60.279,-32.106 -60.232,-32.106 -60.232,-34.628 ; -60.385,-34.647 -59.563,-35.469 ; -60.232,-34.628 cw(c-59.688,-34.085) -60.448,-33.969 ccw(c-59.688,-34.085) -60.232,-34.628 ; -60.232,-34.628 ccw(c-60.703,-35.099) -60.881,-34.457 cw(c-60.703,-35.099) -60.232,-34.628 ; -60.232,-34.628 -60.213,-34.647 ; -60.213,-34.647 cw(c-59.633,-34.067) -60.446,-33.958 ccw(c-59.633,-34.067) -60.213,-34.647 ; -60.213,-34.647 ccw(c-60.716,-35.15) -60.893,-34.461 cw(c-60.716,-35.15) -60.213,-34.647 ; -60.213,-34.647 -59.563,-35.297 ; -59.861,-37.782 -59.668,-37.782 -59.388,-37.502 -59.388,-37.309 ; -59.861,-37.782 -59.799,-37.72 ; -59.799,-37.72 -59.563,-37.484 ; -59.563,-37.484 -59.563,-35.469 ; -59.563,-37.484 -59.388,-37.309 ; -59.563,-35.469 -59.388,-35.644 ; -59.563,-35.469 -59.563,-35.297 ; -59.563,-35.297 -59.388,-35.472 -59.388,-35.644 ; -59.388,-37.309 -59.388,-35.644
NetC48_2: C48.2 R33.1 R36.2 U11.5 | length 10
  Top Layer w0.16: C48.2@-28.656,-12.448 -28.544,-12.561 R36.2@-27.319,-12.561 R33.1@-25.981,-12.561 -25.345,-11.925 U11.5@-25.345,-10.005 ; C48.2@-28.522,-12.708 cw(c-28.167,-13.063) -28.167,-12.561 ; C48.2@-28.522,-12.439 ccw(c-28.228,-12.146) -28.228,-12.561 ; R36.2@-27.453,-12.695 ccw(c-27.777,-13.019) -27.777,-12.561 ccw(c-27.777,-12.102) R36.2@-27.453,-12.426 ; R36.2@-27.184,-12.695 cw(c-26.86,-13.019) -26.86,-12.561 cw(c-26.86,-12.102) R36.2@-27.184,-12.426 ; R33.1@-26.115,-12.695 ccw(c-26.44,-13.019) -26.44,-12.561 ccw(c-26.44,-12.102) R33.1@-26.115,-12.426 ; R33.1@-25.981,-12.358 ccw(c-25.981,-11.868) -25.635,-12.214 ; R33.1@-25.791,-12.548 cw(c-25.363,-12.548) -25.666,-12.245 ; U11.5@-25.501,-10.66 cw(c-25.877,-11.035) -25.345,-11.035 cw(c-24.814,-11.035) U11.5@-25.19,-10.66
NetC50_1: C50.1 R34.2 R37.2 U11.7 | length 10.2
  Top Layer w0.16: R37.2@-23.306,-12.358 ccw(c-23.306,-11.868) -22.959,-12.214 ; R37.2@-23.171,-12.695 cw(c-22.847,-13.019) -22.847,-12.561 cw(c-22.847,-12.102) R37.2@-23.171,-12.426 ; R37.2@-23.116,-12.548 cw(c-22.688,-12.548) -22.99,-12.245 ; U11.7@-22.961,-10.66 cw(c-23.337,-11.035) -22.805,-11.035 cw(c-22.274,-11.035) U11.7@-22.65,-10.66 ; U11.7@-22.805,-10.005 -22.805,-12.061 R37.2@-23.306,-12.561 -22.08,-12.561 C50.1@-21.968,-12.448 -20.742,-12.448 R34.2@-20.63,-12.561 ; -22.458,-12.561 cw(c-22.458,-13.063) C50.1@-22.102,-12.708 ; -22.396,-12.561 ccw(c-22.396,-12.146) C50.1@-22.102,-12.439 ; C50.1@-21.834,-12.583 cw(c-21.509,-12.907) -21.509,-12.448 cw(c-21.509,-11.99) C50.1@-21.834,-12.314 ; -21.329,-12.448 cw(c-21.329,-13.247) R34.2@-20.765,-12.682 ; -20.943,-12.448 cw(c-20.943,-12.86) R34.2@-20.651,-12.569
NetC50_2: C50.2 R35.1 R37.1 U11.6 | length 11.6
  Top Layer w0.16: R35.1@-24.778,-12.414 ccw(c-25.102,-12.089) -24.643,-12.089 ccw(c-24.185,-12.089) R35.1@-24.509,-12.414 ; R35.1@-24.643,-12.764 cw(c-24.643,-13.796) -23.913,-13.066 ; R35.1@-24.643,-12.604 cw(c-24.643,-13.25) -24.186,-12.793 ; U11.6@-24.231,-10.66 cw(c-24.607,-11.035) -24.075,-11.035 cw(c-23.544,-11.035) U11.6@-23.92,-10.66 ; U11.6@-24.075,-10.005 -24.075,-11.18 -24.643,-11.748 R35.1@-24.643,-12.561 -24.418,-12.561 -23.553,-13.426 R37.1@-23.306,-13.426 -22.08,-13.426 C50.2@-21.968,-13.539 ; -24.074,-12.905 ccw(c-23.306,-12.137) R37.1@-23.306,-13.224 ; -23.801,-13.178 ccw(c-23.306,-12.683) R37.1@-23.306,-13.384 ; R37.1@-23.171,-13.561 cw(c-22.847,-13.885) -22.847,-13.426 cw(c-22.847,-12.968) R37.1@-23.171,-13.292 ; -22.458,-13.426 ccw(c-22.458,-12.924) C50.2@-22.102,-13.279 ; -22.396,-13.426 cw(c-22.396,-13.841) C50.2@-22.102,-13.548
NetC51_1: C51.1 R38.1 R41.2 U11.1 | length 9.9
  Top Layer w0.2: R38.1@-23.372,-0.256 -23.259,-0.143 C51.1@-22.034,-0.143 -20.809,-0.143 R41.2@-20.696,-0.256 ; R38.1@-23.251,-0.363 cw(c-22.721,-0.893) -22.721,-0.143 ; C51.1@-22.154,-0.264 ccw(c-22.444,-0.554) -22.444,-0.143 ccw(c-22.444,0.267) C51.1@-22.154,-0.023 ; C51.1@-21.914,-0.264 cw(c-21.624,-0.554) -21.624,-0.143 cw(c-21.624,0.267) C51.1@-21.914,-0.023 ; U11.1@-21.677,-3.365 ccw(c-22.018,-3.023) -21.535,-3.023 ccw(c-21.053,-3.023) U11.1@-21.394,-3.365 ; U11.1@-21.535,-4.006 -21.535,-2.341 -21.304,-2.109 -21.304,-0.147 ; -21.347,-0.143 cw(c-21.347,-0.893) R41.2@-20.816,-0.363
NetC51_2: C51.2 R38.2 R40.1 U11.2 | length 11
  Top Layer w0.2: R40.1@-24.709,-0.256 -24.598,-0.256 -23.732,-1.121 ; -24.299,-0.554 ccw(c-23.372,0.373) R38.2@-23.372,-0.938 ; -23.958,-0.896 ccw(c-23.372,-0.309) R38.2@-23.372,-1.138 ; R38.2@-23.503,-1.229 ccw(c-23.732,-1.419) -23.732,-1.121 ; R38.2@-23.503,-1.013 cw(c-23.732,-0.824) -23.732,-1.121 ; R38.2@-23.251,-1.242 cw(c-22.961,-1.532) -22.961,-1.121 cw(c-22.961,-0.711) R38.2@-23.251,-1.001 ; U11.2@-22.947,-3.365 ccw(c-23.288,-3.023) -22.805,-3.023 ccw(c-22.323,-3.023) U11.2@-22.664,-3.365 ; U11.2@-22.805,-4.006 -22.805,-2.005 C51.2@-22.034,-1.234 -22.146,-1.121 R38.2@-23.372,-1.121 -23.732,-1.121 ; -22.538,-1.737 cw(c-22.034,-2.241) C51.2@-22.034,-1.529 ; -22.475,-1.121 ccw(c-22.475,-0.667) C51.2@-22.154,-0.988 ; -22.413,-1.121 cw(c-22.413,-1.488) C51.2@-22.154,-1.229
NetC54_2: C54.2 R39.1 R42.2 U11.3 | length 12
  Top Layer w0.2: C54.2@-28.722,-0.143 -28.61,-0.256 R42.2@-27.385,-0.256 R39.1@-26.047,-0.256 -25.52,-0.256 -25.382,-0.394 -25.382,-1.848 -25.154,-2.076 -24.5,-2.076 -24.075,-2.501 U11.3@-24.075,-4.006 ; C54.2@-28.602,-0.389 cw(c-28.281,-0.71) -28.281,-0.256 ; C54.2@-28.602,-0.148 ccw(c-28.343,0.111) -28.343,-0.256 ; R42.2@-27.505,-0.376 ccw(c-27.795,-0.666) -27.795,-0.256 ccw(c-27.795,0.155) R42.2@-27.505,-0.135 ; R42.2@-27.264,-0.376 cw(c-26.974,-0.666) -26.974,-0.256 cw(c-26.974,0.155) R42.2@-27.264,-0.135 ; R39.1@-26.167,-0.376 ccw(c-26.457,-0.666) -26.457,-0.256 ccw(c-26.457,0.155) R39.1@-26.167,-0.135 ; R39.1@-25.927,-0.376 cw(c-25.637,-0.666) -25.637,-0.256 cw(c-25.637,0.155) R39.1@-25.927,-0.135 ; U11.3@-24.217,-3.365 ccw(c-24.558,-3.023) -24.075,-3.023 ccw(c-23.593,-3.023) U11.3@-23.934,-3.365
NetC56_1: C56.1 R47.1 | length 2.8
  Top Layer w0.2: R47.1@-20.083,-29.125 C56.1@-18.61,-29.125 ; R47.1@-19.949,-29.245 cw(c-19.659,-29.535) -19.659,-29.125 cw(c-19.659,-28.714) R47.1@-19.949,-29.005 ; C56.1@-18.855,-29.245 ccw(c-19.145,-29.535) -19.145,-29.125 ccw(c-19.145,-28.714) C56.1@-18.855,-29.005
NetC58_1: C58.1 R48.1 | length 3.9
  Top Layer w0.5: R48.1@-16.328,-35.324 ccw(c-16.755,-34.897) -16.151,-34.897 ccw(c-15.546,-34.897) R48.1@-15.974,-35.324 ; C58.1@-16.328,-33.688 cw(c-16.755,-34.116) -16.151,-34.116 cw(c-15.546,-34.116) C58.1@-15.974,-33.688 ; R48.1@-16.151,-35.502 C58.1@-16.151,-33.511
NetC60_1: C60.1 L6.1 R48.2 U13.13 | length 27.5
  Top Layer w0.5: -25.635,-29.781 -25.296,-29.781 -25.114,-29.963 ; -24.718,-30.36 cw(c-24.992,-30.634) v1@-24.604,-30.634 ; -24.58,-33.67 -24.268,-33.67 -24.268,-30.143 -24.934,-30.143 ; v1@-24.564,-30.513 -24.934,-30.143 ; -25.114,-29.963 -25.114,-30.143 -24.934,-30.143 ; -25.114,-29.963 -24.934,-30.143
  Top Layer w1: -25.002,-32.439 -25.002,-32.341 ; -24.712,-34.693 -23.557,-34.693 ; -24.58,-33.67 -23.557,-34.693 ; -23.522,-35.585 -23.522,-35.535 ; -23.379,-34.693 -23.557,-34.693 ; -21.804,-34.693 cw(c-21.804,-36.489) L6.1@-20.257,-35.575 ; L6.1@-21.118,-36.084 ccw(c-23.557,-37.526) -23.557,-34.693 ; L6.1@-20.128,-36.349 -21.784,-34.693 -23.557,-34.693 ; L6.1@-19.315,-38.012 cw(c-18.081,-39.246) -18.081,-37.5 ; L6.1@-19.226,-36.485 ccw(c-17.13,-34.828) -17.13,-37.5 -18.382,-37.5 ; L6.1@-19.224,-37.91 cw(c-18.382,-38.572) -18.382,-37.5 ; L6.1@-18.998,-36.989 ccw(c-18.382,-36.874) -18.382,-37.5
  Bottom Layer w0.254: v1@-24.629,-30.621 C60.1@-23.185,-30.621 ; v1@-24.56,-30.703 cw(c-24.362,-30.901) -24.362,-30.621 ; C60.1@-23.411,-30.722 ccw(c-23.655,-30.966) -23.655,-30.621 ccw(c-23.655,-30.276) C60.1@-23.411,-30.52
  other v1: -24.629,-30.634
NetC60_2: C60.2 U13.14 | length 5.7
  Top Layer w0.2: U13.14@-24.178,-28.222 -23.585,-28.222 -23.216,-28.591 -23.216,-29.427 -22.975,-29.668 v1(-22.095,-29.668) ; v1@-22.183,-29.756 ccw(c-22.397,-29.969) -22.397,-29.668 ccw(c-22.397,-29.366) v1@-22.183,-29.579
  Bottom Layer w0.2: C60.2@-22.215,-30.501 ccw(c-22.505,-30.211) -22.095,-30.211 ccw(c-21.685,-30.211) C60.2@-21.975,-30.501 ; v1@-22.183,-29.756 cw(c-22.397,-29.969) -22.095,-29.969 cw(c-21.793,-29.969) v1@-22.007,-29.756 ; v1@-22.098,-29.665 v1(-22.095,-29.668) C60.2@-22.095,-30.621
NetC61_1: C61.1 C73.2 C74.2 C75.2 C76.2 C77.2 R52.2 R55.1 U13.3 U14.4 | length 61.3
  Top Layer w0.2: C61.1@-35.496,-18.169 -34.344,-18.169 ; C61.1@-35.376,-18.289 cw(c-35.086,-18.579) -35.086,-18.169 cw(c-35.086,-17.758) C61.1@-35.376,-18.049 ; -34.42,-18.955 cw(c-34.42,-19.424) R52.2@-33.952,-19.386 ; -34.383,-19.126 cw(c-34.383,-19.583) R52.2@-33.938,-19.476 ; -34.344,-18.955 ccw(c-34.344,-18.359) R52.2@-33.923,-18.78 ; -34.341,-19.267 cw(c-34.341,-19.729) R52.2@-33.912,-19.557 ; -34.282,-19.267 ccw(c-34.282,-18.785) R52.2@-33.87,-19.034 ; R52.2@-34.217,-19.126 -34.637,-19.126 ; R52.2@-34.203,-18.955 cw(c-34.203,-19.406) R52.2@-33.753,-19.37 ; R52.2@-34.2,-18.955 -34.637,-18.955 ; R52.2@-34.152,-19.402 ccw(c-34.637,-19.441) -34.637,-18.955 ; R52.2@-34.132,-19.523 ccw(c-34.637,-19.645) -34.637,-19.126 ; R52.2@-34.117,-19.1 ccw(c-34.996,-18.821) -34.344,-18.169 ; -34.112,-18.401 cw(c-34.643,-18.933) R52.2@-33.927,-19.16 ; R52.2@-34.098,-19.632 ccw(c-34.637,-19.848) -34.637,-19.267 ; R52.2@-34.041,-18.931 cw(c-34.637,-18.572) -34.637,-19.267 ; R52.2@-34.016,-18.497 ccw(c-33.406,-17.887) R52.2@-33.382,-18.749 ; R52.2@-33.959,-18.818 cw(c-34.637,-18.225) -34.637,-19.126 ; R52.2@-33.447,-18.598 ccw(c-33.59,-18.208) -33.175,-18.208 ; R52.2@-33.388,-18.55 cw(c-33.424,-17.249) -34.344,-18.169 ; R52.2@-32.903,-18.598 cw(c-32.76,-18.208) -33.175,-18.208 ; R52.2@-32.622,-19.481 cw(c-31.92,-19.757) -31.92,-19.003 ; R52.2@-32.52,-18.975 ccw(c-31.922,-18.507) -31.922,-19.267 ; R52.2@-32.471,-19.628 cw(c-31.854,-19.976) -31.854,-19.267 ; R52.2@-32.436,-19.554 cw(c-31.627,-19.873) -31.627,-19.003 ; R52.2@-32.426,-18.78 ccw(c-31.889,-18.243) -31.889,-19.003 ; R52.2@-32.363,-18.852 ccw(c-31.511,-18.186) -31.511,-19.267 ; R52.2@-32.297,-19.726 cw(c-31.511,-20.17) -31.511,-19.267 ; R52.2@-32.25,-19.627 cw(c-31.333,-19.989) -31.333,-19.003 ; R52.2@-32.22,-19.003 -31.333,-19.003 -31.333,-19.083 ; C73.2@-32.033,-25.276 ccw(c-32.323,-24.986) -31.913,-24.986 ccw(c-31.502,-24.986) C73.2@-31.792,-25.276 ; -31.985,-19.083 -31.333,-19.083 ; R55.1@-31.921,-26.502 ccw(c-32.211,-26.212) -31.8,-26.212 ccw(c-31.39,-26.212) R55.1@-31.68,-26.502 ; C73.2@-31.908,-25.516 cw(c-32.167,-25.776) -31.8,-25.776 ; -31.844,-24.418 -31.913,-24.418 -31.913,-24.572 -31.659,-24.572 ; R55.1@-31.8,-26.622 -31.8,-25.508 C73.2@-31.913,-25.396 -31.913,-24.801 ; -31.8,-25.837 cw(c-31.346,-25.837) C73.2@-31.667,-25.516 ; -31.669,-22.611 -31.511,-22.768 ; -31.567,-23.243 -31.511,-23.243 -31.511,-22.768 ; -31.072,-23.08 -31.2,-23.08 -31.333,-22.947 ; U14.4@-30.063,-18.675 ccw(c-30.361,-18.376) -29.939,-18.376 ccw(c-29.516,-18.376) U14.4@-29.815,-18.675 ; U14.4@-29.939,-19.024 -29.939,-18.183 -30.273,-17.849 -32.816,-17.849 -33.175,-18.208 ; -27.324,-24.803 -27.555,-24.572 ; -27.322,-24.544 -27.322,-24.572 -27.555,-24.572 ; U13.3@-27.156,-24.722 cw(c-27.189,-24.206) -27.555,-24.572 ; -34.637,-19.267 -34.637,-19.126 ; -34.637,-19.267 -34.637,-24.573 -32.14,-24.573 ; -34.637,-19.267 R52.2@-33.246,-19.267 ; -34.637,-19.126 -34.637,-18.955 ; -34.344,-18.169 R52.2@-33.246,-19.267 ; R52.2@-33.246,-19.267 R52.2@-33.175,-19.267 ; R52.2@-33.246,-19.267 R52.2@-33.175,-19.338 R52.2@-33.175,-19.267 ; R52.2@-33.175,-19.267 -31.511,-19.267 ; R52.2@-33.175,-19.267 -33.175,-18.208 ; -32.14,-24.573 -31.913,-24.573 -31.913,-24.801 ; -32.14,-24.573 -31.913,-24.801 ; -31.913,-24.801 -31.887,-24.801 -31.659,-24.572 ; -31.659,-24.572 -30.069,-24.572 -29.019,-24.573 -27.555,-24.572 ; -31.511,-22.768 -31.333,-22.947 ; -31.511,-22.768 -31.511,-19.267 ; -31.333,-22.947 -31.333,-19.083
  other v1: -33.83,-24.03 -33.09,-24.03 -31.474,-24.03 -30.702,-24.03 -29.066,-23.87 -28.351,-23.87 -33.514,-22.221 -33.514,-21.537
NetC68_1: C68.1 L6.2 R53.1 U13.12 | length 40.4
  Top Layer w0.5: L6.2@-32.988,-37.292 -32.988,-34.905 L6.2@-32.836,-34.905 ; L6.2@-32.981,-38.564 -32.981,-37.503 -32.836,-37.358 L6.2@-32.836,-34.905 ; L6.2@-31.608,-34.905 L6.2@-32.836,-34.905 ; -28.119,-34.061 -28.185,-34.061 -28.185,-30.135 -27.379,-30.135 ; v1@-27.757,-30.513 -27.379,-30.135 ; -26.963,-29.432 -26.963,-29.719 -27.273,-30.029 ; -27.379,-30.135 -27.273,-30.029 ; -27.379,-30.135 -27.273,-30.135 -27.273,-30.029
  Top Layer w1: -34.07,-37.503 cw(c-34.07,-39.24) L6.2@-32.841,-38.012 ; L6.2@-32.962,-36.527 cw(c-34.865,-35.159) -34.865,-37.503 L6.2@-32.897,-37.503 ; L6.2@-31.894,-35.567 cw(c-30.236,-36.409) -30.236,-34.549 ; L6.2@-31.608,-36.349 L6.2@-31.608,-34.905 ; L6.2@-31.608,-34.35 L6.2@-31.608,-34.905 ; L6.2@-31.149,-34.549 -28.607,-34.549 ; L6.2@-31.028,-36.067 cw(c-28.867,-37.295) -28.867,-34.809 ; L6.2@-31.003,-36.019 cw(c-28.607,-37.236) -28.607,-34.549 ; -27.831,-34.809 -28.867,-34.809 ; -27.701,-33.509 -27.701,-33.644 -28.119,-34.061 -28.607,-34.549 ; -27.61,-34.28 -27.879,-34.549 -28.607,-34.549 ; L6.2@-31.608,-34.905 -31.512,-34.809 -28.867,-34.809 ; -28.867,-34.809 -28.607,-34.549
  Bottom Layer w0.254: C68.1@-28.969,-30.621 v1(-27.789,-30.621) ; C68.1@-28.743,-30.722 cw(c-28.498,-30.966) -28.498,-30.621 cw(c-28.498,-30.276) C68.1@-28.743,-30.52 ; v1@-27.858,-30.69 ccw(c-28.025,-30.858) -28.025,-30.621 ccw(c-28.025,-30.384) v1@-27.858,-30.552
NetC68_2: C68.2 U13.11 | length 6.5
  Top Layer w0.2: v1@-28.976,-28.672 ccw(c-29.189,-28.459) -28.887,-28.459 ccw(c-28.586,-28.459) v1@-28.799,-28.672 ; v1@-28.957,-28.788 cw(c-28.654,-28.67) -28.884,-28.439 ; v1(-28.887,-28.76) -28.887,-28.443 -28.667,-28.222 ; v1@-28.771,-28.715 cw(c-28.341,-28.549) -28.667,-28.222 ; U13.11@-27.978,-28.222 -28.667,-28.222
  Bottom Layer w0.2: C68.2@-30.179,-30.501 ccw(c-30.469,-30.211) -30.059,-30.211 ccw(c-29.648,-30.211) C68.2@-29.939,-30.501 ; C68.2@-30.059,-30.621 -30.059,-29.313 -29.506,-28.76 v1(-28.887,-28.76) ; v1@-28.976,-28.849 ccw(c-29.189,-29.062) -29.189,-28.76 ccw(c-29.189,-28.459) v1@-28.976,-28.672
NetC72_1: C72.1 R53.2 | length 3.9
  Top Layer w0.5: R53.2@-36.099,-35.328 ccw(c-36.525,-34.903) -35.923,-34.903 ccw(c-35.322,-34.903) R53.2@-35.747,-35.328 ; C72.1@-36.1,-33.688 cw(c-36.528,-34.116) -35.923,-34.116 cw(c-35.319,-34.116) C72.1@-35.746,-33.688 ; R53.2@-35.923,-35.504 C72.1@-35.923,-33.511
